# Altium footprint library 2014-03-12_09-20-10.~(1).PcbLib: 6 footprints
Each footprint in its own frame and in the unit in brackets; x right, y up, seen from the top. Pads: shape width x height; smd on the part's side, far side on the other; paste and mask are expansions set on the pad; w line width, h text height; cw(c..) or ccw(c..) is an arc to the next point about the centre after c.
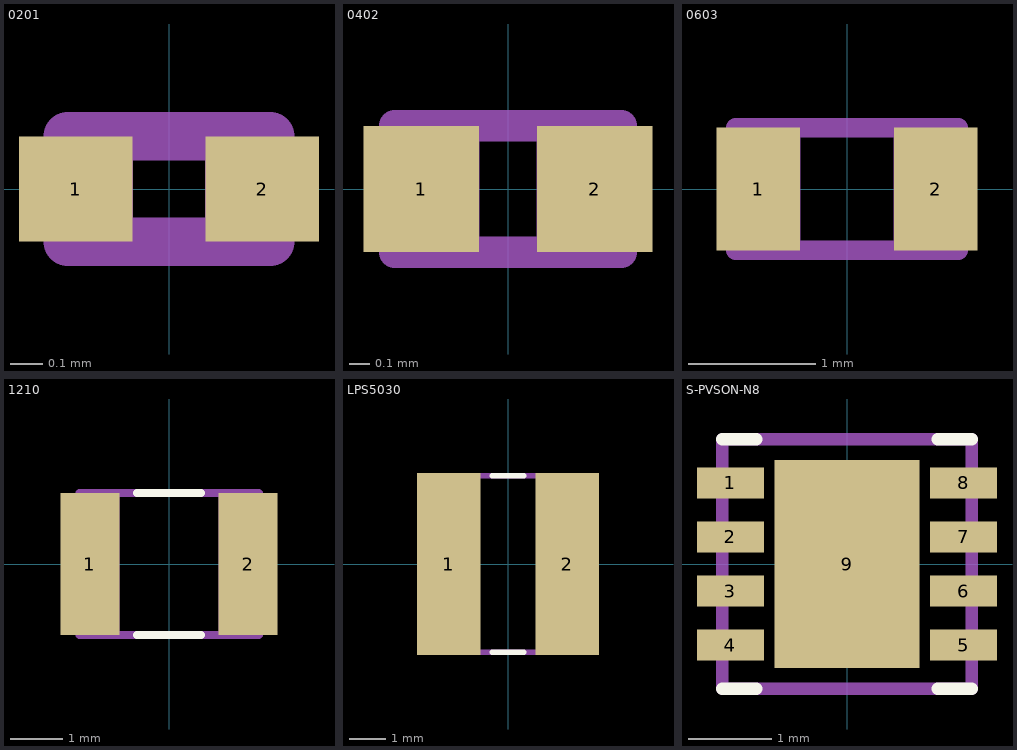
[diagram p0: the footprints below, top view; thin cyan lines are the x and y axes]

## 0201 [mil]
height 13
pads (2):
  rect 14x13 smd: 1(-11.5,0) 2(11.5,0)
Mechanical 1:
  lines w6: -12.5,-6.5 -12.5,6.5 12.5,6.5 12.5,-6.5 -12.5,-6.5
  text "13" at 0,0 h50
Mechanical 13:
  lines w0: -12.5,-6.5 -12.5,6.5 ; -12.5,-6.5 -4.5,-6.5 -4.5,6.5 -12.5,6.5 ; -12.5,-6.5 12.5,-6.5 ; -12.5,-6.5 -12.5,6.5 ; -12.5,6.5 12.5,6.5 ; 12.5,-6.5 4.5,-6.5 4.5,6.5 12.5,6.5 ; 12.5,-6.5 12.5,6.5 ; 12.5,-6.5 12.5,6.5

## 0402 [mil]
height 22
pads (2):
  rect 22x24 smd: 1(-16.5,0) 2(16.5,0)
Mechanical 1:
  lines w6: -21.5,-12 -21.5,12 21.5,12 21.5,-12 -21.5,-12
  text "22" at 0,0 h50
Mechanical 13:
  lines w0: -21.5,-12 -21.5,12 ; -21.5,-12 -5.5,-12 -5.5,12 -21.5,12 ; -21.5,-12 21.5,-12 ; -21.5,-12 -21.5,12 ; -21.5,12 21.5,12 ; 21.5,-12 5.5,-12 5.5,12 21.5,12 ; 21.5,-12 21.5,12 ; 21.5,-12 21.5,12

## 0603 [mil]
height 20
pads (2):
  rect 26x38 smd: 1(-27.5,0) 2(27.5,0)
Mechanical 1:
  lines w6: -34.5,-19 -34.5,19 34.5,19 34.5,-19 -34.5,-19
  text "20" at 0,0 h50
Mechanical 13:
  lines w0: -34.5,-19 -34.5,19 ; -34.5,-19 -14.5,-19 -14.5,19 -34.5,19 ; -34.5,-19 34.5,-19 ; -34.5,-19 -34.5,19 ; -34.5,19 34.5,19 ; 34.5,-19 14.5,-19 14.5,19 34.5,19 ; 34.5,-19 34.5,19 ; 34.5,-19 34.5,19

## 1210 [mil]
height 59
pads (2):
  rect 44x106 smd: 1(-59,0) 2(59,0)
Top Overlay:
  lines w6: -23.9,-53 23.9,-53 ; -23.9,53 23.9,53
Mechanical 1:
  lines w6: -67,-53 -67,53 67,53 67,-53 -67,-53
  text "59" at 0,0 h50
Mechanical 13:
  lines w0: -67,-53 -67,53 ; -67,-53 -37,-53 -37,53 -67,53 ; -67,-53 67,-53 ; -67,-53 -67,53 ; -67,53 67,53 ; 67,-53 37,-53 37,53 67,53 ; 67,-53 67,53 ; 67,-53 67,53

## LPS5030 [mil]
pads (2):
  rect 68.5x197 smd: 1(-64.25,0) 2(64.25,0)
Top Overlay:
  lines w6: -16.9,-96 16.9,-96 ; -16.9,96 16.9,96
Mechanical 1:
  lines w6: -96,-96 96,-96 96,96 -96,96 -96,-96
Mechanical 13:
  lines w0: -96,-47.5 -47.5,-96 47.5,-96 96,-47.5 96,47.5 47.5,96 -47.5,96 -96,47.5 -96,-47.5

## S-PVSON-N8 [mm]
height 1
pads (9):
  rect 0.805x0.37 smd: 1(-1.402,0.975) 2(-1.402,0.325) 3(-1.402,-0.325) 4(-1.402,-0.975) 5(1.402,-0.975) 6(1.402,-0.325) 7(1.402,0.325) 8(1.402,0.975)
  rect 1.75x2.5 smd paste-1.237: 9(0,0)
Top Overlay:
  lines w0.152: -1.5,-1.5 -1.095,-1.5 ; -1.5,1.5 -1.095,1.5 ; 1.095,-1.5 1.5,-1.5 ; 1.095,1.5 1.5,1.5
Top Paste:
  region: 0.875,1.25 -0.875,1.25 -0.875,-1.25 0.875,-1.25
Mechanical 1:
  lines w0.152: -1.5,-1.5 -1.5,1.5 1.5,1.5 1.5,-1.5 -1.5,-1.5
  text "39.37008" at 0,0 h1.27
Mechanical 13:
  lines w0: -1.5,-1.5 1.5,-1.5 1.5,1.5 -1.5,1.5 -1.5,-1.5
